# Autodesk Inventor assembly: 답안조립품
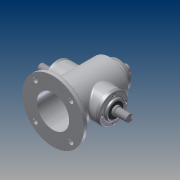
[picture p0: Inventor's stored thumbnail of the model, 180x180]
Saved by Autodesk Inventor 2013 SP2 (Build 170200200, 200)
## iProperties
Created: 2014-12
Part Number: 답안조립품
Document SubType Name: Assembly
Designer: CADB206
Author: CADB206
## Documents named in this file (12)
- C:\Users\CADB206\Desktop\답안조립품.iam
- C:\Users\CADB206\Desktop\본체.ipt
- C:\Users\CADB206\Desktop\커버.ipt
- C:\Users\CADB206\Desktop\오일실.ipt
- 오일실.ipt
- C:\Users\CADB206\Desktop\축.ipt
- C:\Users\CADB206\Desktop\베어링 6002.ipt
- 베어링 6002.ipt
- C:\Users\CADB206\Desktop\슬라이드.ipt
- C:\Users\CADB206\Desktop\M3x0.5x8.ipt
- M3x0.5.ipt
- C:\Users\CADB206\Desktop\상단커버.ipt
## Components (12 placed, 1 different names)
1. M3x0.5:2 — 각도:1
2. M3x0.5:4
3. M3x0.5:5
4. M3x0.5:6
5. M3x0.5:1 — 각도:2
6. M3x0.5:7
7. M3x0.5:8
8. M3x0.5:9
9. M3x0.5:3 — 각도:3
10. M3x0.5:10
11. M3x0.5:11
12. M3x0.5:12
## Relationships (3: Angle 3)
- 각도:1 [Angle]: M3x0.5:2
- 각도:2 [Angle]: M3x0.5:1
- 각도:3 [Angle]: M3x0.5:3
